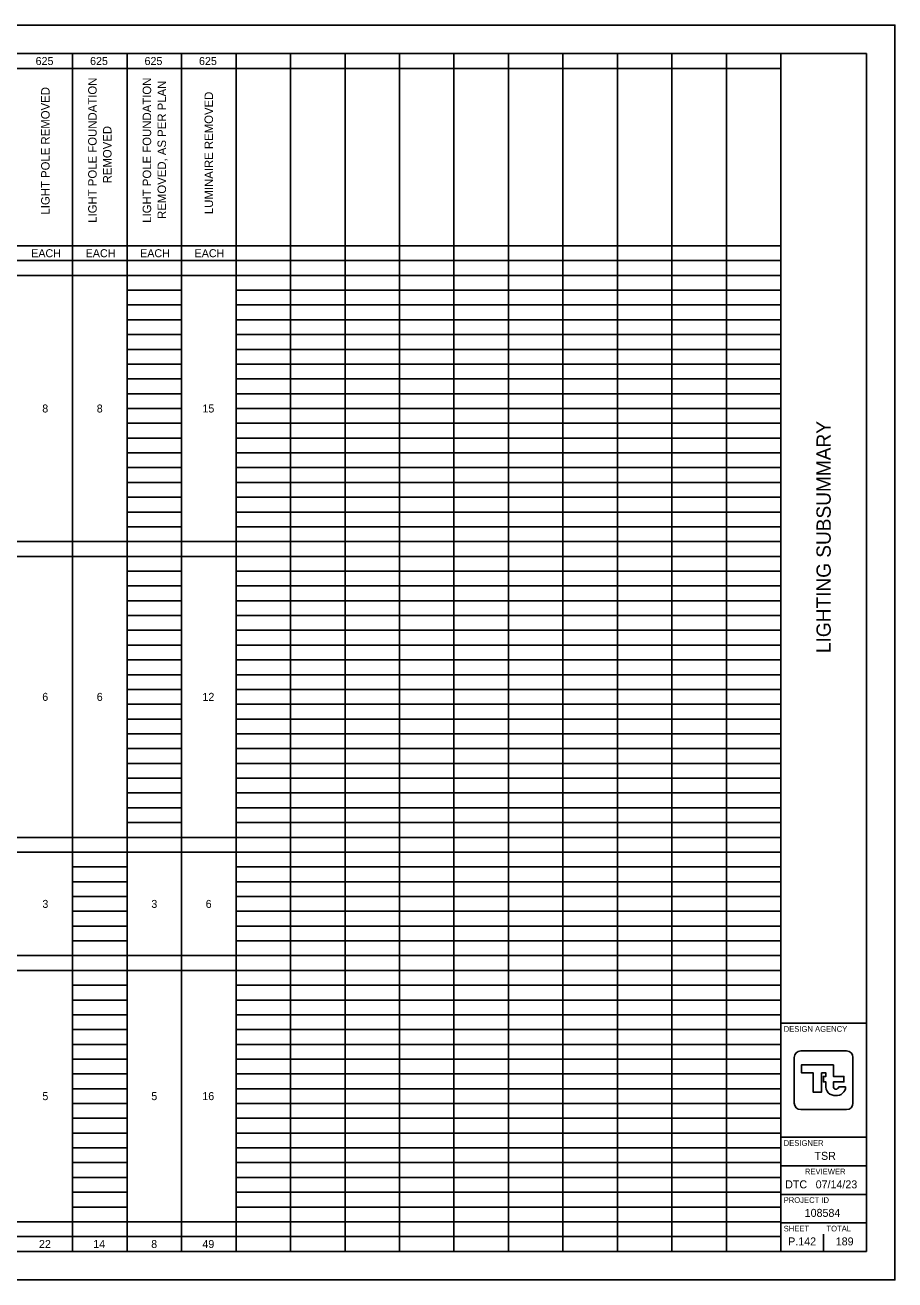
# Model space of a CAD drawing. Extents: x 0 to 34, y 0 to 22.
# Drawn here: x 18.75 to 34, y 0 to 22 of the extents above; entities that cross this region are included whole.
import ezdxf

# ---------------------------------------------------------------- set-up
doc = ezdxf.new("R2010")
doc.units = 0
for name, color, linetype in [('Default', 7, 'Continuous'), ('SH_Border', 7, 'Continuous'), ('SH_Cut_Line', 7, 'Continuous'), ('SH_Data', 7, 'Continuous')]:
    doc.layers.add(name, color=color, linetype=linetype)

msp = doc.modelspace()

# ---------------------------------------------------------------- linework, layer by layer
at = {"layer": 'Default'}
for p, q in [((1.5, 21.5), (32, 21.5)), ((19.583, 21.5), (19.583, 0.759)), ((20.538, 21.5), (20.538, 0.759)), ((21.493, 21.5), (21.493, 0.759)), ((22.449, 21.5), (22.449, 0.759)), ((23.404, 21.5), (23.404, 0.759)), ((24.359, 21.5), (24.359, 0.759)), ((25.314, 21.5), (25.314, 0.759)), ((26.269, 21.5), (26.269, 0.759)), ((27.224, 21.5), (27.224, 0.759)), ((28.179, 21.5), (28.179, 0.759)), ((29.135, 21.5), (29.135, 0.759)), ((30.09, 21.5), (30.09, 0.759)), ((31.045, 21.5), (31.045, 0.759)), ((32, 21.5), (32, 0.759)), ((13.852, 21.241), (32, 21.241)), ((13.852, 18.13), (32, 18.13)), ((1.5, 17.87), (32, 17.87)), ((1.5, 17.611), (32, 17.611)), ((20.538, 17.352), (21.493, 17.352)), ((22.449, 17.352), (32, 17.352)), ((20.538, 17.093), (21.493, 17.093)), ((22.449, 17.093), (32, 17.093)), ((20.538, 16.833), (21.493, 16.833)), ((22.449, 16.833), (32, 16.833)), ((20.538, 16.574), (21.493, 16.574)), ((22.449, 16.574), (32, 16.574)), ((20.538, 16.315), (21.493, 16.315)), ((22.449, 16.315), (32, 16.315)), ((20.538, 16.056), (21.493, 16.056)), ((22.449, 16.056), (32, 16.056)), ((20.538, 15.796), (21.493, 15.796)), ((22.449, 15.796), (32, 15.796)), ((20.538, 15.537), (21.493, 15.537)), ((22.449, 15.537), (32, 15.537)), ((20.538, 15.278), (21.493, 15.278)), ((22.449, 15.278), (32, 15.278)), ((20.538, 15.019), (21.493, 15.019)), ((22.449, 15.019), (32, 15.019)), ((20.538, 14.759), (21.493, 14.759)), ((22.449, 14.759), (32, 14.759)), ((20.538, 14.5), (21.493, 14.5)), ((22.449, 14.5), (32, 14.5)), ((20.538, 14.241), (21.493, 14.241)), ((22.449, 14.241), (32, 14.241)), ((20.538, 13.981), (21.493, 13.981)), ((22.449, 13.981), (32, 13.981)), ((20.538, 13.722), (21.493, 13.722)), ((22.449, 13.722), (32, 13.722)), ((20.538, 13.463), (21.493, 13.463)), ((22.449, 13.463), (32, 13.463)), ((20.538, 13.204), (21.493, 13.204)), ((22.449, 13.204), (32, 13.204)), ((1.5, 12.944), (32, 12.944)), ((1.5, 12.685), (32, 12.685)), ((20.538, 12.426), (21.493, 12.426)), ((22.449, 12.426), (32, 12.426)), ((20.538, 12.167), (21.493, 12.167)), ((22.449, 12.167), (32, 12.167)), ((20.538, 11.907), (21.493, 11.907)), ((22.449, 11.907), (32, 11.907)), ((20.538, 11.648), (21.493, 11.648)), ((22.449, 11.648), (32, 11.648)), ((20.538, 11.389), (21.493, 11.389)), ((22.449, 11.389), (32, 11.389)), ((20.538, 11.13), (21.493, 11.13)), ((22.449, 11.13), (32, 11.13)), ((20.538, 10.87), (21.493, 10.87)), ((22.449, 10.87), (32, 10.87)), ((20.538, 10.611), (21.493, 10.611)), ((22.449, 10.611), (32, 10.611)), ((20.538, 10.352), (21.493, 10.352)), ((22.449, 10.352), (32, 10.352)), ((20.538, 10.093), (21.493, 10.093)), ((22.449, 10.093), (32, 10.093)), ((20.538, 9.833), (21.493, 9.833)), ((22.449, 9.833), (32, 9.833)), ((20.538, 9.574), (21.493, 9.574)), ((22.449, 9.574), (32, 9.574)), ((20.538, 9.315), (21.493, 9.315)), ((22.449, 9.315), (32, 9.315)), ((20.538, 9.056), (21.493, 9.056)), ((22.449, 9.056), (32, 9.056)), ((20.538, 8.796), (21.493, 8.796)), ((22.449, 8.796), (32, 8.796)), ((20.538, 8.537), (21.493, 8.537)), ((22.449, 8.537), (32, 8.537)), ((20.538, 8.278), (21.493, 8.278)), ((22.449, 8.278), (32, 8.278)), ((20.538, 8.019), (21.493, 8.019)), ((22.449, 8.019), (32, 8.019)), ((1.5, 7.759), (32, 7.759)), ((1.5, 7.5), (32, 7.5)), ((19.583, 7.241), (20.538, 7.241)), ((22.449, 7.241), (32, 7.241)), ((19.583, 6.981), (20.538, 6.981)), ((22.449, 6.981), (32, 6.981)), ((19.583, 6.722), (20.538, 6.722)), ((22.449, 6.722), (32, 6.722)), ((19.583, 6.463), (20.538, 6.463)), ((22.449, 6.463), (32, 6.463)), ((19.583, 6.204), (20.538, 6.204)), ((22.449, 6.204), (32, 6.204)), ((19.583, 5.944), (20.538, 5.944)), ((22.449, 5.944), (32, 5.944)), ((1.5, 5.685), (32, 5.685)), ((1.5, 5.426), (32, 5.426)), ((19.583, 5.167), (20.538, 5.167)), ((22.449, 5.167), (32, 5.167)), ((19.583, 4.907), (20.538, 4.907)), ((22.449, 4.907), (32, 4.907)), ((19.583, 4.648), (20.538, 4.648)), ((22.449, 4.648), (32, 4.648)), ((19.583, 4.389), (20.538, 4.389)), ((22.449, 4.389), (32, 4.389)), ((19.583, 4.13), (20.538, 4.13)), ((22.449, 4.13), (32, 4.13)), ((19.583, 3.87), (20.538, 3.87)), ((22.449, 3.87), (32, 3.87)), ((19.583, 3.611), (20.538, 3.611)), ((22.449, 3.611), (32, 3.611)), ((19.583, 3.352), (20.538, 3.352)), ((22.449, 3.352), (32, 3.352)), ((19.583, 3.093), (20.538, 3.093)), ((22.449, 3.093), (32, 3.093)), ((19.583, 2.833), (20.538, 2.833)), ((22.449, 2.833), (32, 2.833)), ((19.583, 2.574), (20.538, 2.574)), ((22.449, 2.574), (32, 2.574)), ((19.583, 2.315), (20.538, 2.315)), ((22.449, 2.315), (32, 2.315)), ((19.583, 2.056), (20.538, 2.056)), ((22.449, 2.056), (32, 2.056)), ((19.583, 1.796), (20.538, 1.796)), ((22.449, 1.796), (32, 1.796)), ((19.583, 1.537), (20.538, 1.537)), ((22.449, 1.537), (32, 1.537)), ((19.583, 1.278), (20.538, 1.278)), ((22.449, 1.278), (32, 1.278)), ((1.5, 1.019), (32, 1.019)), ((1.5, 0.759), (32, 0.759)), ((19.583, 0.759), (19.583, 0.5)), ((20.538, 0.759), (20.538, 0.5)), ((21.493, 0.759), (21.493, 0.5)), ((22.449, 0.759), (22.449, 0.5)), ((23.404, 0.759), (23.404, 0.5)), ((24.359, 0.759), (24.359, 0.5)), ((25.314, 0.759), (25.314, 0.5)), ((26.269, 0.759), (26.269, 0.5)), ((27.224, 0.759), (27.224, 0.5)), ((28.179, 0.759), (28.179, 0.5)), ((29.135, 0.759), (29.135, 0.5)), ((30.09, 0.759), (30.09, 0.5)), ((31.045, 0.759), (31.045, 0.5)), ((32, 0.759), (32, 0.5)), ((1.5, 0.5), (32, 0.5))]:
    msp.add_line(p, q, dxfattribs=at)
at = {"layer": 'SH_Border'}
for p, q in [((32, 0.5), (32, 21.5)), ((32, 4.5), (33.5, 4.5)), ((32, 2.5), (33.5, 2.5)), ((32, 2), (33.5, 2)), ((32, 1.5), (33.5, 1.5)), ((32, 1), (33.5, 1))]:
    msp.add_line(p, q, dxfattribs=at)
msp.add_lwpolyline([(1.5, 21.5), (33.5, 21.5), (33.5, 0.5), (1.5, 0.5)], close=True, dxfattribs=at)
at = {"layer": 'SH_Cut_Line'}
msp.add_lwpolyline([(0, 0), (34, 0), (34, 22), (0, 22)], close=True, dxfattribs=at)
at = {"layer": 'SH_Data'}
for p, q in [((32.75, 3.5), (32.75, 3.5)), ((32.791, 3.415), (32.791, 3.415)), ((33.136, 3.385), (33.015, 3.385)), ((32.375, 0.675), (32.375, 0.675)), ((32.75, 0.5), (32.75, 0.8))]:
    msp.add_line(p, q, dxfattribs=at)
for points in [[(32.348, 4.014), (33.152, 4.014)], [(32.236, 3.099), (32.236, 3.901)], [(32.922, 3.399), (32.922, 3.47), (33.107, 3.47), (33.107, 3.568), (32.922, 3.568), (32.922, 3.768), (32.361, 3.768), (32.361, 3.632), (32.566, 3.632), (32.566, 3.294), (32.715, 3.294), (32.715, 3.63), (32.79, 3.63), (32.79, 3.568), (32.748, 3.568), (32.748, 3.47), (32.79, 3.47), (32.79, 3.415), (32.791, 3.415)], [(33.264, 3.901), (33.264, 3.099)], [(33.152, 2.986), (32.348, 2.986)]]:
    msp.add_lwpolyline(points, dxfattribs=at)
for centre, radius, start, end in [((32.348, 3.901), 0.113, 90, 180), ((33.152, 3.901), 0.113, 360, 90), ((32.949, 3.392), 0.16, 171.8856, 274.8323), ((32.968, 3.392), 0.0473, 171.8856, 350.9243), ((32.976, 3.392), 0.16, 265.1677, 357.3201), ((32.348, 3.099), 0.113, 180, 270), ((33.152, 3.099), 0.113, 270, 360)]:
    msp.add_arc(centre, radius, start, end, dxfattribs=at)

# ---------------------------------------------------------------- texts
at = {"layer": 'Default'}
for s, height, p in [('625', 0.1403, (18.934, 21.3)), ('625', 0.1403, (19.889, 21.3)), ('625', 0.1403, (20.844, 21.3)), ('625', 0.1403, (21.799, 21.3)), ('EACH', 0.1403, (18.857, 17.93)), ('EACH', 0.1403, (19.812, 17.93)), ('EACH', 0.1403, (20.767, 17.93)), ('EACH', 0.1403, (21.722, 17.93)), ('8', 0.14, (19.051, 15.208)), ('8', 0.14, (20.006, 15.208)), ('15', 0.1403, (21.859, 15.208)), ('6', 0.14, (19.051, 10.152)), ('6', 0.14, (20.006, 10.152)), ('12', 0.1403, (21.859, 10.152)), ('3', 0.14, (19.053, 6.522)), ('3', 0.14, (20.963, 6.522)), ('6', 0.14, (21.916, 6.522)), ('5', 0.14, (19.053, 3.152)), ('5', 0.14, (20.963, 3.152)), ('16', 0.1403, (21.857, 3.152)), ('22', 0.1403, (18.993, 0.559)), ('14', 0.1403, (19.945, 0.559)), ('8', 0.14, (20.961, 0.559)), ('49', 0.1403, (21.858, 0.559))]:
    msp.add_text(s, height=height, dxfattribs=at).set_placement(p)
for s, height, p in [('LIGHT POLE REMOVED', 0.14894, (19.18, 18.678)), ('LIGHT POLE FOUNDATION ', 0.14894, (20.005, 18.534)), ('LIGHT POLE FOUNDATION ', 0.14894, (20.96, 18.534)), ('REMOVED, AS PER PLAN', 0.14894, (21.221, 18.602)), ('LUMINAIRE REMOVED', 0.14894, (22.045, 18.686)), ('REMOVED', 0.1489, (20.265, 19.225))]:
    msp.add_text(s, height=height, rotation=90, dxfattribs=at).set_placement(p)
at = {"layer": 'SH_Data'}
msp.add_text('LIGHTING SUBSUMMARY', height=0.25, rotation=90, dxfattribs=at).set_placement((32.875, 10.99))
for s, height, p in [('DESIGN AGENCY', 0.1, (32.05, 4.35)), ('DESIGNER', 0.1, (32.05, 2.35)), ('TSR', 0.14, (32.59, 2.105)), ('REVIEWER', 0.1, (32.422, 1.85)), ('DTC', 0.14, (32.076, 1.605)), ('07/14/23', 0.14, (32.611, 1.605)), ('PROJECT ID', 0.1, (32.05, 1.35)), ('108584', 0.14, (32.418, 1.105)), ('SHEET', 0.1, (32.05, 0.85)), ('TOTAL', 0.1, (32.8, 0.85)), ('P.142', 0.14, (32.129, 0.605)), ('189', 0.14, (32.963, 0.605))]:
    msp.add_text(s, height=height, dxfattribs=at).set_placement(p)

doc.saveas('drawing.dxf')
